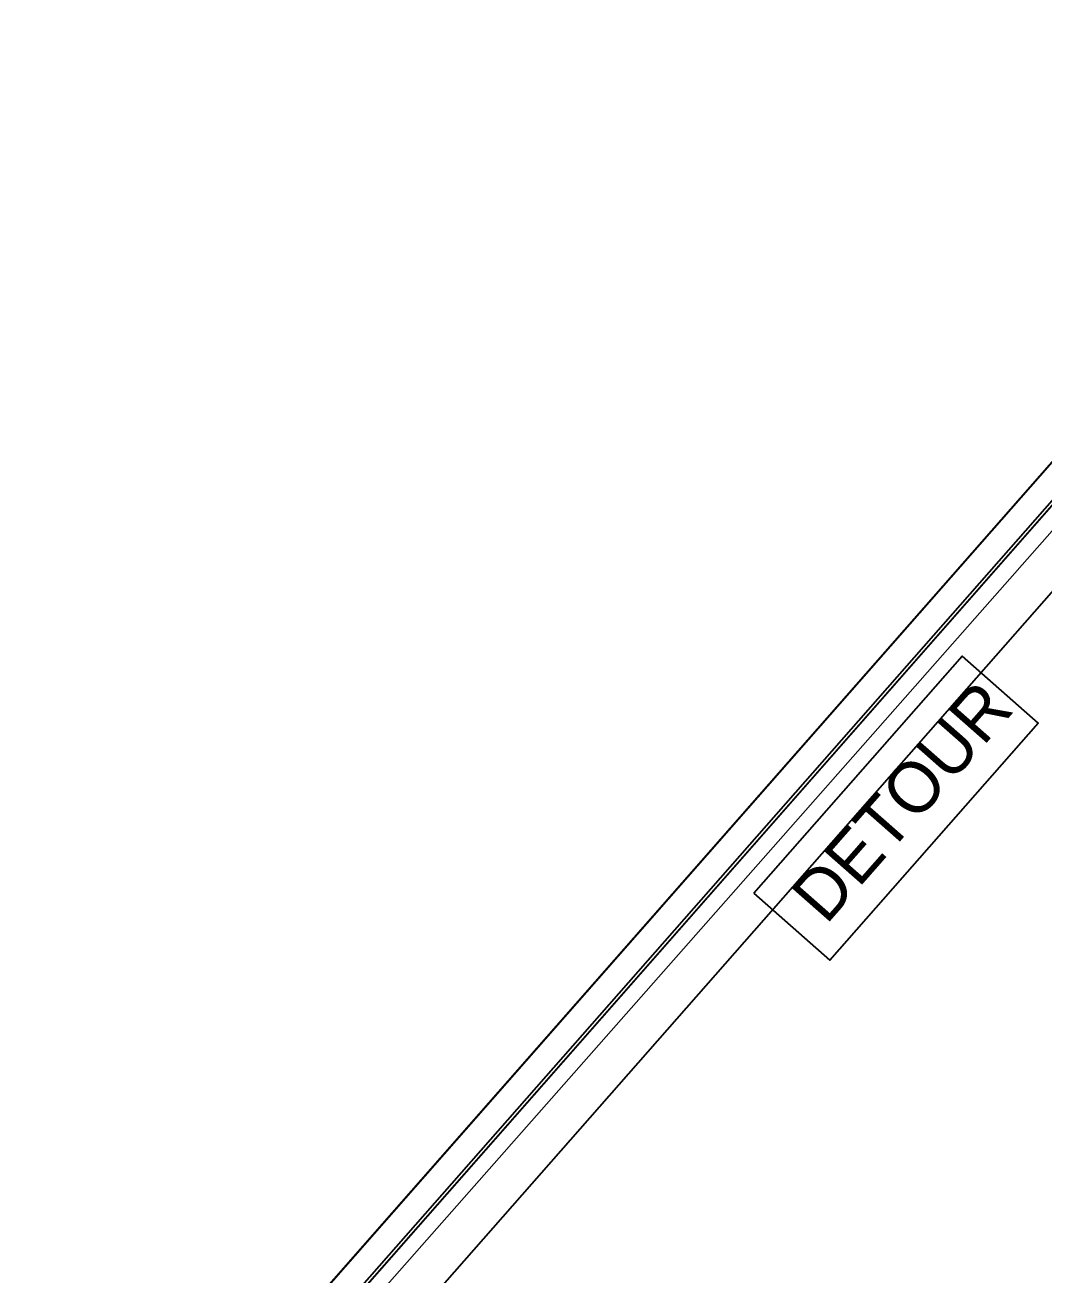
# Model space of a CAD drawing. Extents: x 2189835 to 2191772, y 387461 to 389531.
# Drawn here: x 2189835 to 2190636, y 388465 to 389448 of the extents above; entities that cross this region are included whole.
import ezdxf

# ---------------------------------------------------------------- set-up
doc = ezdxf.new("R2010")
doc.units = 0
for name, color, linetype in [('Prop Grid Mask', 7, 'Continuous'), ('Prop RDY Alternate Text Yellow', 7, 'Continuous'), ('Sheet Clip Boundary CELL', 7, 'Continuous'), ('Sheet Cutting Line CELL', 7, 'Continuous'), ('Sheet Layout Plan Border', 7, 'Continuous'), ('Sheet Plan CELL', 7, 'Continuous'), ('Sheet Plan Layout CELL', 7, 'Continuous'), ('Sheet Plot Border Inside CELL', 7, 'Continuous'), ('Sheet Plot Border Outside CELL', 7, 'Continuous')]:
    doc.layers.add(name, color=color, linetype=linetype)

msp = doc.modelspace()

# ---------------------------------------------------------------- linework, layer by layer
at = {"layer": 'Prop Grid Mask'}
msp.add_lwpolyline([(2190408.52, 388764.84), (2190572.64, 388951.53), (2190632.66, 388898.76), (2190468.53, 388712.08)], close=True, dxfattribs=at)
at = {"layer": 'Sheet Clip Boundary CELL'}
msp.add_lwpolyline([(2190233.88, 388250.3), (2190718.45, 387881.26), (2190850.4, 387777.99), (2191678.63, 388725.5), (2191058.62, 389246.4), (2190957.74, 389128.02), (2190818.15, 389247.91), (2190051.03, 388378.47)], close=True, dxfattribs=at)
at = {"layer": 'Sheet Cutting Line CELL'}
msp.add_line((2190946.11, 389448.37), (2189834.54, 388184.02), dxfattribs=at)
at = {"layer": 'Sheet Layout Plan Border'}
msp.add_lwpolyline([(2190847.19, 387643.49), (2191771.58, 388694.94), (2191141.84, 389248.59), (2191016.87, 389106.45), (2190858.04, 389246.09), (2190058.62, 388336.78)], close=True, dxfattribs=at)
at = {"layer": 'Sheet Plan CELL'}
for points in [[(2190951.79, 389420.78), (2189961.36, 388294.21), (2190749.93, 387600.92), (2191740.35, 388727.47)], [(2190749.93, 387600.92), (2189961.36, 388294.17), (2190819.67, 389270.52), (2190932.38, 389171.45), (2191064.47, 389321.68), (2191740.35, 388727.47)]]:
    msp.add_lwpolyline(points, close=True, dxfattribs=at)
at = {"layer": 'Sheet Plan Layout CELL'}
msp.add_lwpolyline([(2189961.36, 388294.17), (2190749.93, 387600.92), (2191740.34, 388727.46), (2191110.6, 389281.11), (2190952.63, 389101.43), (2190793.79, 389241.07)], close=True, dxfattribs=at)
at = {"layer": 'Sheet Plot Border Inside CELL'}
msp.add_lwpolyline([(2190650.48, 387483.99), (2191750.47, 388735.2), (2190958.16, 389431.79), (2189858.14, 388180.58)], close=True, dxfattribs=at)
at = {"layer": 'Sheet Plot Border Outside CELL'}
msp.add_lwpolyline([(2190656.91, 387461.02), (2191768.48, 388725.38), (2190946.11, 389448.37), (2189834.54, 388184.02)], close=True, dxfattribs=at)

# ---------------------------------------------------------------- texts
at = {"layer": 'Prop RDY Alternate Text Yellow'}
msp.add_text('DETOUR', height=40, rotation=48.67944, dxfattribs=at).set_placement((2190465.5, 388739.28))

doc.saveas('drawing.dxf')
